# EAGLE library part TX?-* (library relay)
TX Relais NAiS TX-D RELAYS HIGH INSULATION Conforming to the supplementary insulation class of EN Standards (EN41003) Source: http://www.mew-europe.com/.. en_ds_61022_0007.pdf TX-S RELAYS SMALL POLARIZED RELAY WITH HIGH SENSITIVITY 50mW Source: http://www.mew-europe.com/.. en_ds_61022_0022.pdf
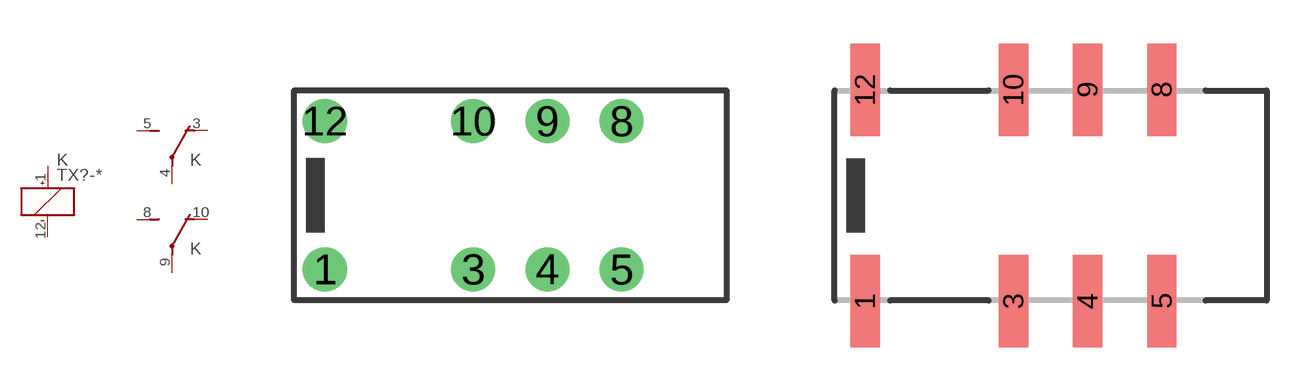
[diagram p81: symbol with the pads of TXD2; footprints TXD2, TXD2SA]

Designator prefix K; gates _=K+- G$1=U G$2=U

## TXD2-1.5V (OC_FARNELL: unknown; OC_NEWARK: unknown), TXD2-3V (MPN: TXD2-3V; OC_FARNELL: unknown; OC_NEWARK: 13P9524), TXD2-4.5V (OC_FARNELL: unknown; OC_NEWARK: unknown), TXD2-5V (MPN: TXD2-5V; OC_FARNELL: unknown; OC_NEWARK: 13P9525), TXD2-6V (OC_FARNELL: unknown; OC_NEWARK: unknown), TXD2-9V (OC_FARNELL: unknown; OC_NEWARK: unknown), TXD2-12V (MPN: TXD2-12V; OC_FARNELL: unknown; OC_NEWARK: 13P9522), TXD2-24V (MPN: TXD2-24V; OC_FARNELL: unknown; OC_NEWARK: 13P9523)  [TXD2]
1  _:+  pas
3  G$1:O  pas
4  G$1:P  pas
5  G$1:S  pas
8  G$2:S  pas
9  G$2:P  pas
10  G$2:O  pas
12  _:-  pas

## TXD2SA-1.5V (OC_FARNELL: unknown; OC_NEWARK: unknown), TXD2SA-3V (MF: AROMAT/ MATSUSHITA; MPN: TXD2SA-3V; OC_FARNELL: unknown; OC_NEWARK: 11C0176), TXD2SA-4.5V (MPN: TXD2SA-4.5V; OC_FARNELL: unknown; OC_NEWARK: 13P9531), TXD2SA-5V (MPN: TXD2SA-5V; OC_FARNELL: unknown; OC_NEWARK: 13P9532), TXD2SA-6V (MPN: TXD2SA-6V; OC_FARNELL: unknown; OC_NEWARK: 13P9534), TXD2SA-9V (OC_FARNELL: unknown; OC_NEWARK: unknown), TXD2SA-12V (MPN: TXD2SA-12V; OC_FARNELL: unknown; OC_NEWARK: 13P9526), TXD2SA-24V (OC_FARNELL: unknown; OC_NEWARK: unknown)  [TXD2SA]
Pads as for TXD2

## TXD2SL-1.5V (OC_FARNELL: unknown; OC_NEWARK: unknown), TXD2SL-3V (MF: AROMAT/ MATSUSHITA; MPN: TXD2SL-3V; OC_FARNELL: unknown; OC_NEWARK: 11C0248), TXD2SL-4.5V (MPN: TXD2SL-4.5V-X; OC_FARNELL: unknown; OC_NEWARK: 11N6056), TXD2SL-5V (OC_FARNELL: unknown; OC_NEWARK: unknown), TXD2SL-6V (OC_FARNELL: unknown; OC_NEWARK: unknown), TXD2SL-9V (OC_FARNELL: unknown; OC_NEWARK: unknown), TXD2SL-12V (OC_FARNELL: unknown; OC_NEWARK: unknown), TXD2SL-24V (OC_FARNELL: unknown; OC_NEWARK: unknown)  [TXD2SL]
Pads as for TXD2

## TXD2SS-1.5V (OC_FARNELL: unknown; OC_NEWARK: unknown), TXD2SS-3V (MF: AROMAT/ MATSUSHITA; MPN: TXD2SS-3V; OC_FARNELL: unknown; OC_NEWARK: 11C0320), TXD2SS-4.5V (OC_FARNELL: unknown; OC_NEWARK: unknown), TXD2SS-5V (MF: AROMAT/ MATSUSHITA; MPN: TXD2SS-5V; OC_FARNELL: unknown; OC_NEWARK: 11C0326), TXD2SS-6V (OC_FARNELL: unknown; OC_NEWARK: unknown), TXD2SS-9V (OC_FARNELL: unknown; OC_NEWARK: unknown), TXD2SS-12V (MPN: TXD2SS-12V-Z; OC_FARNELL: unknown; OC_NEWARK: 13P9535), TXD2SS-24V (MPN: TXD2SS-24V-Z; OC_FARNELL: unknown; OC_NEWARK: 13P9536)  [TXD2SS]
Pads as for TXD2

## TXD2-L-1.5V (OC_FARNELL: unknown; OC_NEWARK: unknown), TXD2-L-3V (OC_FARNELL: unknown; OC_NEWARK: unknown), TXD2-L-4.5V (MF: AROMAT/ MATSUSHITA; MPN: TXD2-L-4.5V; OC_FARNELL: unknown; OC_NEWARK: 11C0103), TXD2-L-5V (OC_FARNELL: unknown; OC_NEWARK: unknown), TXD2-L-6V (OC_FARNELL: unknown; OC_NEWARK: unknown), TXD2-L-9V (OC_FARNELL: unknown; OC_NEWARK: unknown), TXD2-L-12V (OC_FARNELL: unknown; OC_NEWARK: unknown), TXD2-L-24V (OC_FARNELL: unknown; OC_NEWARK: unknown)  [TXD2]
1  _:-  pas
3  G$1:O  pas
4  G$1:P  pas
5  G$1:S  pas
8  G$2:S  pas
9  G$2:P  pas
10  G$2:O  pas
12  _:+  pas

## TXD2SA-L-1.5V (OC_FARNELL: unknown; OC_NEWARK: unknown), TXD2SA-L-3V (OC_FARNELL: unknown; OC_NEWARK: unknown), TXD2SA-L-4.5V (OC_FARNELL: unknown; OC_NEWARK: unknown), TXD2SA-L-5V (OC_FARNELL: unknown; OC_NEWARK: unknown), TXD2SA-L-6V (OC_FARNELL: unknown; OC_NEWARK: unknown), TXD2SA-L-9V (OC_FARNELL: unknown; OC_NEWARK: unknown), TXD2SA-L-12V (OC_FARNELL: unknown; OC_NEWARK: unknown), TXD2SA-L-24V (OC_FARNELL: unknown; OC_NEWARK: unknown)  [TXD2SA]
Pads as for TXD2

## TXD2SL-L-1.5V (OC_FARNELL: unknown; OC_NEWARK: unknown), TXD2SL-L-3V (OC_FARNELL: unknown; OC_NEWARK: unknown), TXD2SL-L-4.5V (OC_FARNELL: unknown; OC_NEWARK: unknown), TXD2SL-L-5V (MPN: TXD2SL-L-5V; OC_FARNELL: unknown; OC_NEWARK: 15P9960), TXD2SL-L-6V (OC_FARNELL: unknown; OC_NEWARK: unknown), TXD2SL-L-9V (OC_FARNELL: unknown; OC_NEWARK: unknown), TXD2SL-L-12V (MPN: TXD2SL-L-12V; OC_FARNELL: unknown; OC_NEWARK: 15P9956), TXD2SL-L-24V (MPN: TXD2SL-L-24V; OC_FARNELL: unknown; OC_NEWARK: 15P9958)  [TXD2SL]
Pads as for TXD2

## TXD2SS-L-1.5V (OC_FARNELL: unknown; OC_NEWARK: unknown), TXD2SS-L-3V (OC_FARNELL: unknown; OC_NEWARK: unknown), TXD2SS-L-4.5V (OC_FARNELL: unknown; OC_NEWARK: unknown), TXD2SS-L-5V (OC_FARNELL: unknown; OC_NEWARK: unknown), TXD2SS-L-6V (OC_FARNELL: unknown; OC_NEWARK: unknown), TXD2SS-L-9V (OC_FARNELL: unknown; OC_NEWARK: unknown), TXD2SS-L-12V (OC_FARNELL: unknown; OC_NEWARK: unknown), TXD2SS-L-24V (OC_FARNELL: unknown; OC_NEWARK: unknown)  [TXD2SS]
Pads as for TXD2

## TXD2-2M-1.5V (OC_FARNELL: unknown; OC_NEWARK: unknown), TXD2-2M-3V (OC_FARNELL: unknown; OC_NEWARK: unknown), TXD2-2M-4.5V (OC_FARNELL: unknown; OC_NEWARK: unknown), TXD2-2M-5V (OC_FARNELL: unknown; OC_NEWARK: unknown), TXD2-2M-6V (OC_FARNELL: unknown; OC_NEWARK: unknown), TXD2-2M-9V (OC_FARNELL: unknown; OC_NEWARK: unknown), TXD2-2M-12V (OC_FARNELL: unknown; OC_NEWARK: unknown), TXD2-2M-24V (OC_FARNELL: unknown; OC_NEWARK: unknown)  [TXD2]
Pads as for TXD2

## TXD2SA-2M-1.5V (OC_FARNELL: unknown; OC_NEWARK: unknown), TXD2SA-2M-3V (OC_FARNELL: unknown; OC_NEWARK: unknown), TXD2SA-2M-4.5V (OC_FARNELL: unknown; OC_NEWARK: unknown), TXD2SA-2M-5V (OC_FARNELL: unknown; OC_NEWARK: unknown), TXD2SA-2M-6V (OC_FARNELL: unknown; OC_NEWARK: unknown), TXD2SA-2M-9V (OC_FARNELL: unknown; OC_NEWARK: unknown), TXD2SA-2M-12V (OC_FARNELL: unknown; OC_NEWARK: unknown), TXD2SA-2M-24V (OC_FARNELL: unknown; OC_NEWARK: unknown)  [TXD2SA]
Pads as for TXD2

## TXD2SL-2M-1.5V (OC_FARNELL: unknown; OC_NEWARK: unknown), TXD2SL-2M-3V (OC_FARNELL: unknown; OC_NEWARK: unknown), TXD2SL-2M-4.5V (OC_FARNELL: unknown; OC_NEWARK: unknown), TXD2SL-2M-5V (OC_FARNELL: unknown; OC_NEWARK: unknown), TXD2SL-2M-6V (OC_FARNELL: unknown; OC_NEWARK: unknown), TXD2SL-2M-9V (OC_FARNELL: unknown; OC_NEWARK: unknown), TXD2SL-2M-12V (OC_FARNELL: unknown; OC_NEWARK: unknown), TXD2SL-2M-24V (OC_FARNELL: unknown; OC_NEWARK: unknown)  [TXD2SL]
Pads as for TXD2

## TXD2SS-2M-1.5V (OC_FARNELL: unknown; OC_NEWARK: unknown), TXD2SS-2M-3V (OC_FARNELL: unknown; OC_NEWARK: unknown), TXD2SS-2M-4.5V (OC_FARNELL: unknown; OC_NEWARK: unknown), TXD2SS-2M-5V (OC_FARNELL: unknown; OC_NEWARK: unknown), TXD2SS-2M-6V (OC_FARNELL: unknown; OC_NEWARK: unknown), TXD2SS-2M-9V (OC_FARNELL: unknown; OC_NEWARK: unknown), TXD2SS-2M-12V (MF: AROMAT/ MATSUSHITA; MPN: TXD2SS-2M-12V; OC_FARNELL: unknown; OC_NEWARK: 11C0296), TXD2SS-2M-24V (OC_FARNELL: unknown; OC_NEWARK: unknown)  [TXD2SS]
Pads as for TXD2

## TXS2-1.5V (OC_FARNELL: unknown; OC_NEWARK: unknown), TXS2-3V (MPN: TXS2-3V; OC_FARNELL: unknown; OC_NEWARK: 13P9541), TXS2-4.5V (MPN: TXS2-4.5V; OC_FARNELL: 1608335; OC_NEWARK: 13P9542), TXS2-5V (OC_FARNELL: unknown; OC_NEWARK: unknown), TXS2-6V (MPN: TXS2-6V; OC_FARNELL: unknown; OC_NEWARK: 13P9543), TXS2-9V (MPN: TXS2-9V; OC_FARNELL: unknown; OC_NEWARK: 11N6058), TXS2-12V (MPN: TXS2-12V; OC_FARNELL: unknown; OC_NEWARK: 13P9539), TXS2-24V (MPN: TXS2-24V; OC_FARNELL: unknown; OC_NEWARK: 13P9540)  [TXD2]
Pads as for TXD2

## TXS2-L-1.5V (MPN: TXS2-L-1.5V; OC_FARNELL: unknown; OC_NEWARK: 12N3844), TXS2-L-3V (MPN: TXS2-L-3V; OC_FARNELL: unknown; OC_NEWARK: 15P9962), TXS2-L-4.5V (MPN: TXS2-L-4.5V; OC_FARNELL: unknown; OC_NEWARK: 15P9963), TXS2-L-5V (OC_FARNELL: unknown; OC_NEWARK: unknown), TXS2-L-6V (OC_FARNELL: unknown; OC_NEWARK: unknown), TXS2-L-9V (MPN: TXS2-L-9V; OC_FARNELL: unknown; OC_NEWARK: 12N3848), TXS2-L-12V (MPN: TXS2-L-12V; OC_FARNELL: unknown; OC_NEWARK: 12N3845), TXS2-L-24V (MPN: TXS2-L-24V; OC_FARNELL: unknown; OC_NEWARK: 12N3846)  [TXD2]
Pads as for TXD2

## TXS2SA--1.5V (MPN: TXS2SA-1.5V; OC_FARNELL: unknown; OC_NEWARK: 11N6059), TXS2SA--3V (MPN: TXS2SA-3V; OC_FARNELL: unknown; OC_NEWARK: 11N6066), TXS2SA--4.5V (MPN: TXS2SA-4.5V; OC_FARNELL: unknown; OC_NEWARK: 13P9550), TXS2SA--5V (OC_FARNELL: unknown; OC_NEWARK: unknown), TXS2SA--6V (MPN: TXS2SA-6V; OC_FARNELL: unknown; OC_NEWARK: 13P9552), TXS2SA--9V (MF: AROMAT/ MATSUSHITA; MPN: TXS2SA-9V; OC_FARNELL: unknown; OC_NEWARK: 97H8371), TXS2SA--12V (MPN: TXS2SA-12V; OC_FARNELL: 1231846; OC_NEWARK: 13P9545), TXS2SA--24V (MF: AROMAT/ MATSUSHITA; MPN: TXS2SA-24V; OC_FARNELL: unknown; OC_NEWARK: 11C0345)  [TXD2SA]
Pads as for TXD2

## TXS2SL--1.5V (MPN: TXS2SL-1.5V; OC_FARNELL: unknown; OC_NEWARK: 11N6074), TXS2SL--3V (MPN: TXS2SL-3V-Z; OC_FARNELL: unknown; OC_NEWARK: 13P9555), TXS2SL--4.5V (MPN: TXS2SL-4.5V; OC_FARNELL: unknown; OC_NEWARK: 13P9556), TXS2SL--5V (OC_FARNELL: unknown; OC_NEWARK: unknown), TXS2SL--6V (MPN: TXS2SL-6V; OC_FARNELL: unknown; OC_NEWARK: 11N6087), TXS2SL--9V (MPN: TXS2SL-9V; OC_FARNELL: unknown; OC_NEWARK: 11N6090), TXS2SL--12V (MPN: TXS2SL-12V; OC_FARNELL: unknown; OC_NEWARK: 11N6077), TXS2SL--24V (MPN: TXS2SL-24V; OC_FARNELL: unknown; OC_NEWARK: 11N6081)  [TXD2SL]
Pads as for TXD2

## TXS2SS--1.5V (MPN: TXS2SS-1.5V; OC_FARNELL: unknown; OC_NEWARK: 11N6094), TXS2SS--3V (MPN: TXS2SS-3V-Z; OC_FARNELL: unknown; OC_NEWARK: 13P9564), TXS2SS--4.5V (MPN: TXS2SS-4.5V; OC_FARNELL: unknown; OC_NEWARK: 13P9565), TXS2SS--5V (OC_FARNELL: unknown; OC_NEWARK: unknown), TXS2SS--6V (MPN: TXS2SS-6V; OC_FARNELL: unknown; OC_NEWARK: 11N6103), TXS2SS--9V (MPN: TXS2SS-9V; OC_FARNELL: unknown; OC_NEWARK: 11N6106), TXS2SS--12V (MPN: TXS2SS-12V; OC_FARNELL: unknown; OC_NEWARK: 13P9561), TXS2SS--24V (MPN: TXS2SS-24V-Z; OC_FARNELL: unknown; OC_NEWARK: 13P9563)  [TXD2SS]
Pads as for TXD2

## TXS2SA-L--1.5V (MPN: TXS2SA-L-1.5V; OC_FARNELL: unknown; OC_NEWARK: 12N3853), TXS2SA-L--3V (MPN: TXS2SA-L-3V; OC_FARNELL: unknown; OC_NEWARK: 12N3862), TXS2SA-L--4.5V (MPN: TXS2SA-L-4.5V; OC_FARNELL: unknown; OC_NEWARK: 15P9968), TXS2SA-L--5V (MPN: TXS2SA-L-5V; OC_FARNELL: unknown; OC_NEWARK: 12N3867), TXS2SA-L--6V (MPN: TXS2SA-L-6V; OC_FARNELL: unknown; OC_NEWARK: 12N3870), TXS2SA-L--9V (MPN: TXS2SA-L-9V; OC_FARNELL: unknown; OC_NEWARK: 12N3873), TXS2SA-L--12V (MPN: TXS2SA-L-12V; OC_FARNELL: unknown; OC_NEWARK: 12N3856), TXS2SA-L--24V (MPN: TXS2SA-L-24V; OC_FARNELL: unknown; OC_NEWARK: 12N3859)  [TXD2SA]
Pads as for TXD2

## TXS2SL-L-1.5V (MPN: TXS2SL-L-1.5V; OC_FARNELL: unknown; OC_NEWARK: 12N3892), TXS2SL-L-3V (MPN: TXS2SL-L-3V; OC_FARNELL: unknown; OC_NEWARK: 12N3902), TXS2SL-L-4.5V (MPN: TXS2SL-L-4.5V; OC_FARNELL: unknown; OC_NEWARK: 12N3905), TXS2SL-L-5V (OC_FARNELL: unknown; OC_NEWARK: unknown), TXS2SL-L-6V (MPN: TXS2SL-L-6V; OC_FARNELL: unknown; OC_NEWARK: 12N3908), TXS2SL-L-9V (MPN: TXS2SL-L-9V; OC_FARNELL: unknown; OC_NEWARK: 12N3911), TXS2SL-L-12V (MPN: TXS2SL-L-12V; OC_FARNELL: unknown; OC_NEWARK: 12N3895), TXS2SL-L-24V (MPN: TXS2SL-L-24V; OC_FARNELL: unknown; OC_NEWARK: 12N3898)  [TXD2SL]
Pads as for TXD2

## TXS2SS-L-1.5V (MPN: TXS2SS-L-1.5V; OC_FARNELL: unknown; OC_NEWARK: 12N3933), TXS2SS-L-3V (MPN: TXS2SS-L-3V; OC_FARNELL: unknown; OC_NEWARK: 12N3942), TXS2SS-L-4.5V (MPN: TXS2SS-L-4.5V; OC_FARNELL: unknown; OC_NEWARK: 12N3945), TXS2SS-L-5V (OC_FARNELL: unknown; OC_NEWARK: unknown), TXS2SS-L-6V (MPN: TXS2SS-L-6V; OC_FARNELL: unknown; OC_NEWARK: 12N3948), TXS2SS-L-9V (MPN: TXS2SS-L-9V; OC_FARNELL: unknown; OC_NEWARK: 12N3951), TXS2SS-L-12V (MPN: TXS2SS-L-12V; OC_FARNELL: unknown; OC_NEWARK: 12N3936), TXS2SS-L-24V (MPN: TXS2SS-L-24V; OC_FARNELL: unknown; OC_NEWARK: 12N3939)  [TXD2SS]
Pads as for TXD2

## Footprint TXD2 (pad centres in mm)
HIGH INSULATION RELAYS NAiS Conforming to the supplementary insulation class of EN Standards (EN41003) Source: http://www.mew-europe.com/.. en_ds_61022_0007.pdf
drill 1 round: 1 -6.35,-2.54; 3 -1.27,-2.54; 4 1.27,-2.54; 5 3.81,-2.54; 8 3.81,2.54; 9 1.27,2.54; 10 -1.27,2.54; 12 -6.35,2.54

## Footprint TXD2SA (pad centres in mm)
HIGH INSULATION RELAYS NAiS Conforming to the supplementary insulation class of EN Standards (EN41003) Source: http://www.mew-europe.com/.. en_ds_61022_0007.pdf
smd 1 x 3.16: 1 -6.35,-3.62; 3 -1.27,-3.62; 4 1.27,-3.62; 5 3.81,-3.62; 8 3.81,3.62; 9 1.27,3.62; 10 -1.27,3.62; 12 -6.35,3.62

## Footprint TXD2SL (pad centres in mm)
HIGH INSULATION RELAYS NAiS Conforming to the supplementary insulation class of EN Standards (EN41003) Source: http://www.mew-europe.com/.. en_ds_61022_0007.pdf
smd 1 x 3.16: 1 -6.35,-3.62; 3 -1.27,-3.62; 4 1.27,-3.62; 5 3.81,-3.62; 8 3.81,3.62; 9 1.27,3.62; 10 -1.27,3.62; 12 -6.35,3.62

## Footprint TXD2SS (pad centres in mm)
HIGH INSULATION RELAYS NAiS Conforming to the supplementary insulation class of EN Standards (EN41003) Source: http://www.mew-europe.com/.. en_ds_61022_0007.pdf
smd 1 x 2.16: 1 -6.35,-3.12; 3 -1.27,-3.12; 4 1.27,-3.12; 5 3.81,-3.12; 8 3.81,3.12; 9 1.27,3.12; 10 -1.27,3.12; 12 -6.35,3.12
